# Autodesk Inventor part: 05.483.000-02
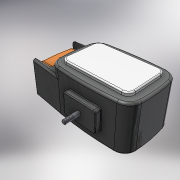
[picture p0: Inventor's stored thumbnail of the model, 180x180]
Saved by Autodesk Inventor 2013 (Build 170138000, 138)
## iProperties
Created: 2005-07
Part Number: 05.483.000-02
Material: Steel, Mild
Document SubType Name: Modeling
Designer: tedescj
Manufacturer: Standard
Standards Organization: Custom
Density: 7.86 g/cm^3
Author: PVitaliy
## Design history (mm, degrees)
derived "05.483.000-01.ipt"
feature "Solid1::05.483.000-01.ipt" dims "d0" = 10
tag "TaggingFeature1"
body "Solid1"
